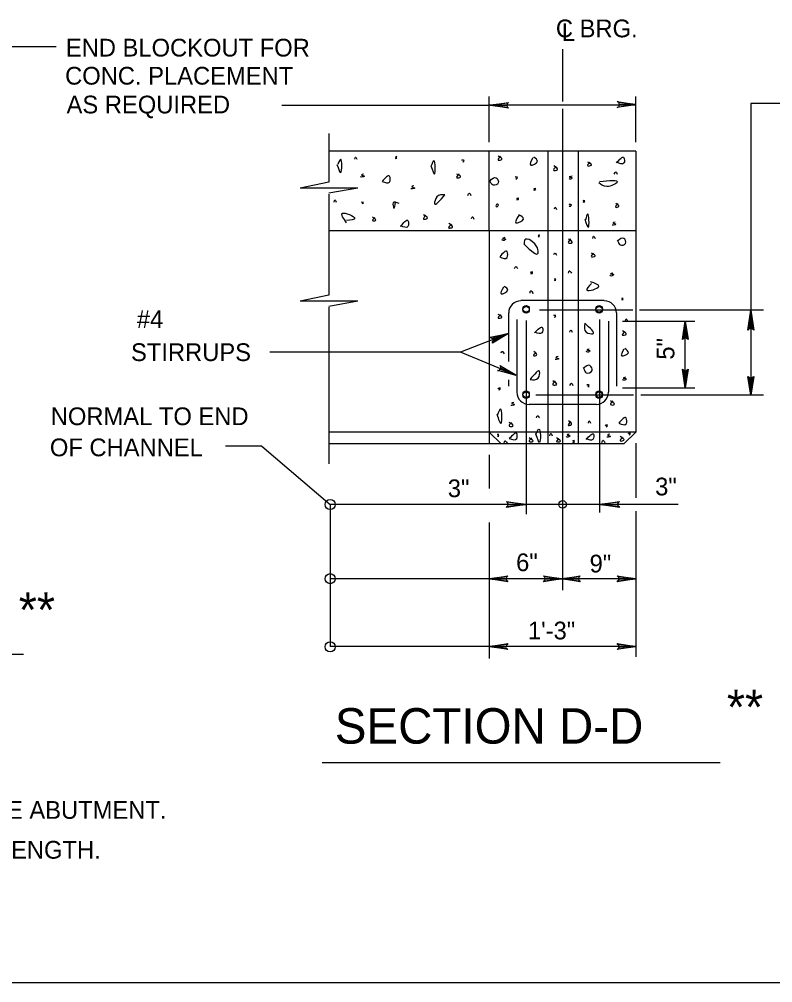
# Model space of a CAD drawing. Extents: x 642009 to 642864, y 298232 to 300014.
# Drawn here: x 642295.7 to 642423.1, y 299434.8 to 299597.7 of the extents above; entities that cross this region are included whole.
import ezdxf

# ---------------------------------------------------------------- set-up
doc = ezdxf.new("R2010")
doc.units = 0
doc.layers.add('1', color=7, linetype='Continuous')
doc.layers.add('2', color=7, linetype='Continuous')

msp = doc.modelspace()

# ---------------------------------------------------------------- linework, layer by layer
at = {"layer": '1'}
msp.add_line((642336.76, 299525.57), (642348.29, 299515.7), dxfattribs=at)
for centre, radius in [((642348.29, 299515.7), 0.854), ((642387.57, 299515.7), 0.648), ((642348.29, 299503.15), 0.854), ((642348.29, 299491.63), 0.854)]:
    msp.add_circle(centre, radius, dxfattribs=at)
at = {"layer": '2'}
for p, q in [((642301.98, 299593.08), (642263.61, 299593.08)), ((642387.57, 299592.7), (642387.57, 299583.83)), ((642375.19, 299576.95), (642375.19, 299584.7)), ((642399.94, 299576.95), (642399.94, 299584.7)), ((642419.39, 299583.49), (642419.39, 299534.2)), ((642426.75, 299583.49), (642419.39, 299583.49)), ((642340.14, 299583.2), (642375.19, 299583.2)), ((642399.94, 299583.2), (642375.19, 299583.2)), ((642387.57, 299582.58), (642387.57, 299501.2)), ((642348.07, 299578.45), (642348.07, 299570.2)), ((642399.94, 299575.45), (642348.07, 299575.45)), ((642375.19, 299561.95), (642375.19, 299575.33)), ((642385.07, 299575.45), (642385.07, 299525.95)), ((642390.19, 299575.45), (642390.19, 299525.95)), ((642399.94, 299575.45), (642399.94, 299527.95)), ((642348.07, 299570.2), (642343.19, 299569.2)), ((642352.94, 299569.2), (642343.19, 299569.2)), ((642352.94, 299569.2), (642348.07, 299568.33)), ((642348.07, 299568.2), (642348.07, 299551.08)), ((642399.94, 299561.95), (642348.07, 299561.95)), ((642375.19, 299561.95), (642375.19, 299527.95)), ((642348.07, 299551.08), (642343.19, 299550.08)), ((642352.94, 299550.08), (642343.19, 299550.08)), ((642352.94, 299550.08), (642348.07, 299549.2)), ((642394.62, 299550.2), (642380.52, 299550.2)), ((642348.07, 299549.08), (642348.07, 299522.58)), ((642378.45, 299548.08), (642378.45, 299539.88)), ((642381.44, 299548.58), (642381.44, 299548.58)), ((642399.44, 299548.58), (642383.69, 299548.58)), ((642393.82, 299548.58), (642393.82, 299548.58)), ((642396.68, 299548.08), (642396.68, 299535.7)), ((642403.69, 299548.58), (642400.57, 299548.58)), ((642417.89, 299548.58), (642403.69, 299548.58)), ((642421.53, 299548.58), (642417.89, 299548.58)), ((642379.82, 299546.95), (642379.82, 299534.7)), ((642381.44, 299546.83), (642381.44, 299514.08)), ((642393.82, 299546.95), (642393.82, 299514.33)), ((642395.32, 299546.7), (642395.32, 299534.7)), ((642397.68, 299546.7), (642402.44, 299546.7)), ((642402.44, 299546.7), (642409.94, 299546.7)), ((642408.32, 299535.45), (642408.32, 299546.7)), ((642378.45, 299544.61), (642370.32, 299541.45)), ((642370.32, 299541.45), (642338.08, 299541.45)), ((642379.69, 299537.58), (642370.32, 299541.45)), ((642378.45, 299536.78), (642378.45, 299535.7)), ((642397.69, 299535.45), (642402.44, 299535.45)), ((642402.44, 299535.45), (642409.94, 299535.45)), ((642381.44, 299534.2), (642381.44, 299534.2)), ((642381.44, 299534.2), (642381.44, 299534.2)), ((642381.44, 299534.2), (642381.44, 299534.2)), ((642399.57, 299534.2), (642383.07, 299534.2)), ((642393.82, 299534.2), (642393.82, 299534.2)), ((642393.82, 299534.2), (642393.82, 299534.2)), ((642403.69, 299534.2), (642400.82, 299534.2)), ((642417.89, 299534.2), (642403.69, 299534.2)), ((642421.53, 299534.2), (642408.07, 299534.2)), ((642393.32, 299532.58), (642381.94, 299532.58)), ((642375.19, 299528.08), (642375.19, 299525.95)), ((642375.19, 299527.95), (642348.07, 299527.95)), ((642375.19, 299527.95), (642377.19, 299525.95)), ((642399.94, 299527.95), (642375.19, 299527.95)), ((642399.94, 299527.95), (642397.94, 299525.95)), ((642336.76, 299525.57), (642330.62, 299525.57)), ((642377.57, 299525.95), (642348.07, 299525.95)), ((642397.94, 299525.95), (642376.57, 299525.95)), ((642399.94, 299526.08), (642399.94, 299516.82)), ((642375.19, 299524.08), (642375.19, 299518.42)), ((642381.44, 299515.7), (642348.29, 299515.7)), ((642348.29, 299515.7), (642348.29, 299491.66)), ((642387.44, 299515.7), (642381.44, 299515.7)), ((642407.13, 299515.7), (642387.69, 299515.7)), ((642399.94, 299514.58), (642399.94, 299489.91)), ((642375.19, 299512.63), (642375.19, 299489.66)), ((642381.44, 299503.14), (642348.29, 299503.14)), ((642399.94, 299503.14), (642375.19, 299503.14)), ((642375.19, 299491.66), (642348.29, 299491.66)), ((642399.94, 299491.66), (642375.19, 299491.66)), ((642208.18, 299490.4), (642296.43, 299490.4)), ((642346.94, 299472.07), (642414.19, 299472.07)), ((642834.66, 299434.82), (642048.66, 299434.82))]:
    msp.add_line(p, q, dxfattribs=at)
for points in [[(642378.32, 299582.83), (642378.19, 299583.08), (642375.32, 299583.2), (642378.32, 299582.83), (642378.44, 299582.7), (642375.32, 299583.2), (642378.19, 299583.33), (642378.32, 299583.58), (642375.32, 299583.2), (642378.44, 299583.7), (642378.32, 299583.58)], [(642397.07, 299583.7), (642397.07, 299583.45), (642399.94, 299583.33), (642397.07, 299583.7), (642396.82, 299583.83), (642399.94, 299583.33), (642397.07, 299583.2), (642397.07, 299582.95), (642399.94, 299583.33), (642396.82, 299582.83), (642397.07, 299582.95)], [(642419.01, 299545.33), (642419.26, 299545.45), (642419.39, 299548.58), (642419.01, 299545.33), (642418.89, 299545.2), (642419.39, 299548.58), (642419.51, 299545.45), (642419.76, 299545.33), (642419.39, 299548.58), (642419.89, 299545.2), (642419.76, 299545.33)], [(642407.94, 299543.7), (642408.19, 299543.83), (642408.32, 299546.7), (642407.94, 299543.7), (642407.82, 299543.58), (642408.32, 299546.7), (642408.44, 299543.83), (642408.69, 299543.7), (642408.32, 299546.7), (642408.82, 299543.58), (642408.69, 299543.7)], [(642375.45, 299543.86), (642375.7, 299543.74), (642378.45, 299544.61), (642375.45, 299543.86), (642375.33, 299543.99), (642378.45, 299544.61), (642375.83, 299543.49), (642375.7, 299543.24), (642378.45, 299544.61), (642375.7, 299542.99), (642375.7, 299543.24)], [(642377.07, 299539.08), (642377.07, 299538.83), (642379.69, 299537.58), (642377.07, 299539.08), (642376.94, 299539.2), (642379.69, 299537.58), (642376.94, 299538.58), (642376.82, 299538.33), (642379.69, 299537.58), (642376.57, 299538.33), (642376.82, 299538.33)], [(642408.69, 299538.45), (642408.44, 299538.33), (642408.32, 299535.45), (642408.69, 299538.45), (642408.82, 299538.58), (642408.32, 299535.45), (642408.19, 299538.33), (642407.94, 299538.45), (642408.32, 299535.45), (642407.82, 299538.58), (642407.94, 299538.45)], [(642419.76, 299537.2), (642419.51, 299537.08), (642419.39, 299534.2), (642419.76, 299537.2), (642419.89, 299537.33), (642419.39, 299534.2), (642419.26, 299537.08), (642419.01, 299537.2), (642419.39, 299534.2), (642418.89, 299537.33), (642419.01, 299537.2)], [(642378.19, 299516.08), (642378.32, 299515.83), (642381.44, 299515.7), (642378.19, 299516.08), (642378.07, 299516.2), (642381.44, 299515.7), (642378.32, 299515.58), (642378.19, 299515.33), (642381.44, 299515.7), (642378.07, 299515.2), (642378.19, 299515.33)], [(642397.07, 299515.33), (642396.94, 299515.58), (642393.82, 299515.7), (642397.07, 299515.33), (642397.19, 299515.2), (642393.82, 299515.7), (642396.94, 299515.83), (642397.07, 299516.08), (642393.82, 299515.7), (642397.19, 299516.2), (642397.07, 299516.08)], [(642378.19, 299502.77), (642378.07, 299503.02), (642375.19, 299503.14), (642378.19, 299502.77), (642378.32, 299502.64), (642375.19, 299503.14), (642378.07, 299503.27), (642378.19, 299503.52), (642375.19, 299503.14), (642378.32, 299503.64), (642378.19, 299503.52)], [(642384.44, 299503.52), (642384.57, 299503.27), (642387.44, 299503.14), (642384.44, 299503.52), (642384.32, 299503.64), (642387.44, 299503.14), (642384.57, 299503.02), (642384.44, 299502.77), (642387.44, 299503.14), (642384.32, 299502.64), (642384.44, 299502.77)], [(642390.44, 299502.77), (642390.32, 299503.02), (642387.44, 299503.14), (642390.44, 299502.77), (642390.57, 299502.64), (642387.44, 299503.14), (642390.32, 299503.27), (642390.44, 299503.52), (642387.44, 299503.14), (642390.57, 299503.64), (642390.44, 299503.52)], [(642396.94, 299503.52), (642397.07, 299503.27), (642399.94, 299503.14), (642396.94, 299503.52), (642396.82, 299503.64), (642399.94, 299503.14), (642397.07, 299503.02), (642396.94, 299502.77), (642399.94, 299503.14), (642396.82, 299502.64), (642396.94, 299502.77)], [(642378.19, 299491.28), (642378.07, 299491.41), (642375.19, 299491.66), (642378.19, 299491.28), (642378.32, 299491.16), (642375.19, 299491.66), (642378.07, 299491.78), (642378.19, 299492.03), (642375.19, 299491.66), (642378.32, 299492.16), (642378.19, 299492.03)], [(642396.94, 299492.03), (642397.07, 299491.78), (642399.94, 299491.66), (642396.94, 299492.03), (642396.82, 299492.16), (642399.94, 299491.66), (642397.07, 299491.53), (642396.94, 299491.28), (642399.94, 299491.66), (642396.82, 299491.16), (642396.94, 299491.28)]]:
    msp.add_lwpolyline(points, dxfattribs=at)
for centre in [(642381.4, 299548.78), (642393.77, 299548.78), (642381.4, 299548.61), (642393.77, 299548.61), (642381.4, 299534.34), (642381.4, 299534.17), (642393.77, 299534.34), (642393.77, 299534.17)]:
    msp.add_circle(centre, 0.549, dxfattribs=at)
for centre, start, end in [((642380.52, 299548.08), 90, 180), ((642394.62, 299548.08), 0, 90), ((642381.91, 299534.68), 180, 270), ((642393.26, 299534.68), 270, 0)]:
    msp.add_arc(centre, 2.06, start, end, dxfattribs=at)
for points in [[(642349.44, 299573.2), (642350.07, 299571.83), (642350.07, 299574.08), (642349.57, 299573.2)], [(642352.44, 299574.08), (642352.57, 299574.45), (642352.82, 299574.08)], [(642359.57, 299574.2), (642359.32, 299574.2), (642359.57, 299574.33), (642359.32, 299574.45), (642359.57, 299574.58)], [(642365.32, 299572.95), (642365.94, 299571.58), (642365.82, 299573.83), (642365.32, 299572.83)], [(642370.82, 299573.58), (642370.69, 299573.58), (642370.94, 299573.83), (642370.57, 299573.95), (642370.94, 299573.95)], [(642377.07, 299574.58), (642376.69, 299573.95), (642377.32, 299574.08), (642376.69, 299574.58)], [(642382.57, 299574.33), (642382.19, 299573.08), (642383.32, 299573.7), (642382.69, 299574.45)], [(642396.69, 299573.45), (642397.94, 299574.33), (642397.94, 299573.45), (642396.69, 299573.58)], [(642386.44, 299572.83), (642386.07, 299572.2), (642386.69, 299572.33), (642386.07, 299572.95)], [(642392.19, 299573.58), (642391.82, 299572.95), (642392.44, 299573.08), (642391.82, 299573.58)], [(642353.94, 299571.58), (642353.57, 299571.45), (642354.07, 299571.2), (642353.69, 299571.08), (642353.44, 299571.08)], [(642357.07, 299570.33), (642358.32, 299571.2), (642358.32, 299570.2), (642357.07, 299570.33)], [(642370.07, 299571.58), (642369.69, 299570.95), (642370.32, 299571.08), (642369.69, 299571.58)], [(642375.32, 299570.45), (642375.82, 299569.7), (642376.69, 299570.08), (642376.32, 299570.95), (642375.32, 299570.45)], [(642379.82, 299570.7), (642379.69, 299570.7), (642379.94, 299570.95), (642379.57, 299571.08), (642379.94, 299571.08)], [(642389.19, 299571.2), (642388.69, 299571.08), (642389.19, 299570.95), (642388.82, 299570.7), (642388.69, 299570.83)], [(642393.82, 299570.33), (642396.82, 299570.2), (642395.07, 299569.45), (642393.69, 299570.08)], [(642396.32, 299571.58), (642396.57, 299571.95), (642396.82, 299571.58)], [(642362.44, 299569.58), (642362.07, 299569.45), (642362.57, 299569.2), (642362.19, 299569.08), (642361.94, 299569.08)], [(642382.94, 299568.83), (642382.69, 299568.83), (642383.07, 299569.08), (642382.69, 299569.08), (642383.07, 299569.2)], [(642348.94, 299566.83), (642349.07, 299567.2), (642349.32, 299566.83)], [(642367.69, 299568.08), (642365.94, 299566.58), (642366.32, 299567.7), (642367.69, 299568.08)], [(642371.57, 299567.95), (642371.82, 299568.33), (642372.07, 299567.95)], [(642380.07, 299567.2), (642379.82, 299567.2), (642380.19, 299567.33), (642379.82, 299567.45), (642380.19, 299567.58)], [(642353.94, 299566.58), (642353.69, 299566.58), (642353.94, 299566.7), (642353.57, 299566.83), (642353.94, 299566.83)], [(642359.94, 299566.58), (642358.94, 299566.7), (642359.07, 299565.83), (642359.32, 299566.83)], [(642376.32, 299566.08), (642376.32, 299566.33), (642376.69, 299566.45), (642376.57, 299566.08), (642376.32, 299566.08)], [(642386.19, 299565.7), (642386.32, 299565.95), (642386.57, 299565.58)], [(642388.94, 299566.08), (642388.69, 299566.08), (642389.07, 299566.33), (642388.69, 299566.45), (642389.07, 299566.45)], [(642391.32, 299566.83), (642391.07, 299566.83), (642391.32, 299566.95), (642391.07, 299567.08), (642391.32, 299567.08)], [(642396.94, 299566.58), (642396.57, 299565.95), (642397.07, 299566.08), (642396.57, 299566.58)], [(642351.07, 299563.33), (642350.32, 299564.95), (642352.44, 299564.08), (642351.07, 299563.7)], [(642355.82, 299564.2), (642355.44, 299563.7), (642355.94, 299563.7), (642355.44, 299564.33)], [(642360.19, 299562.7), (642361.44, 299563.7), (642361.44, 299562.7), (642360.19, 299562.83)], [(642364.44, 299564.58), (642364.07, 299563.95), (642364.69, 299564.08), (642364.07, 299564.7)], [(642372.19, 299564.08), (642372.32, 299564.33), (642372.57, 299563.95)], [(642380.19, 299564.58), (642379.69, 299563.33), (642380.94, 299563.95), (642380.19, 299564.7)], [(642391.32, 299563.95), (642391.94, 299562.58), (642391.82, 299564.83), (642391.44, 299563.83)], [(642368.82, 299563.08), (642368.32, 299562.45), (642368.94, 299562.58), (642368.32, 299563.2)], [(642396.44, 299563.45), (642396.07, 299563.33), (642396.57, 299563.08), (642396.19, 299562.95), (642395.94, 299562.95)], [(642377.82, 299560.83), (642377.44, 299560.7), (642377.94, 299560.58), (642377.57, 299560.33), (642377.32, 299560.45)], [(642381.19, 299559.58), (642383.44, 299558.2), (642383.32, 299559.08), (642381.19, 299560.45), (642381.07, 299559.58)], [(642383.69, 299560.95), (642383.44, 299560.95), (642383.69, 299561.2), (642383.44, 299561.2), (642383.69, 299561.33)], [(642392.69, 299560.7), (642392.82, 299561.08), (642393.07, 299560.7)], [(642396.94, 299560.2), (642397.32, 299559.58), (642398.19, 299559.83), (642397.94, 299560.7), (642396.82, 299560.2)], [(642388.94, 299560.58), (642388.57, 299559.95), (642389.19, 299559.95), (642388.57, 299560.58)], [(642376.94, 299557.58), (642378.19, 299558.45), (642378.19, 299557.45), (642376.94, 299557.58)], [(642386.07, 299557.95), (642386.19, 299558.2), (642386.57, 299557.83)], [(642392.82, 299558.2), (642392.44, 299557.58), (642393.07, 299557.7), (642392.44, 299558.2)], [(642379.44, 299555.58), (642379.69, 299555.95), (642379.94, 299555.58)], [(642382.44, 299554.7), (642382.19, 299554.7), (642382.57, 299554.83), (642382.19, 299554.95), (642382.57, 299555.08)], [(642388.57, 299554.83), (642388.69, 299555.2), (642389.07, 299554.83)], [(642396.07, 299554.83), (642395.69, 299554.7), (642396.19, 299554.58), (642395.82, 299554.33), (642395.57, 299554.45)], [(642377.57, 299552.45), (642377.19, 299551.33), (642378.32, 299551.95), (642377.69, 299552.58)], [(642386.44, 299553.58), (642386.19, 299553.58), (642386.44, 299553.7), (642386.19, 299553.83), (642386.44, 299553.83)], [(642392.44, 299553.08), (642391.69, 299551.95), (642393.69, 299552.58), (642392.32, 299553.33)], [(642382.07, 299551.45), (642382.19, 299551.83), (642382.57, 299551.33)], [(642397.82, 299550.33), (642397.57, 299550.33), (642397.82, 299550.45), (642397.57, 299550.58), (642397.82, 299550.58)], [(642377.07, 299547.83), (642376.69, 299547.2), (642377.32, 299547.33), (642376.69, 299547.83)], [(642386.32, 299547.33), (642386.19, 299547.33), (642386.44, 299547.58), (642386.07, 299547.7), (642386.44, 299547.7)], [(642391.32, 299546.33), (642392.69, 299544.58), (642391.57, 299544.83), (642391.32, 299546.33)], [(642398.19, 299546.7), (642398.32, 299547.08), (642398.57, 299546.7)], [(642382.82, 299544.7), (642384.19, 299545.58), (642384.07, 299544.7), (642382.94, 299544.83)], [(642388.82, 299544.83), (642388.94, 299545.2), (642389.19, 299544.83)], [(642398.07, 299544.95), (642397.69, 299544.33), (642398.32, 299544.45), (642397.69, 299545.08)], [(642377.19, 299541.33), (642377.32, 299541.58), (642377.69, 299541.2)], [(642383.07, 299541.45), (642382.69, 299540.83), (642383.19, 299540.95), (642382.69, 299541.58)], [(642392.07, 299541.95), (642391.69, 299541.83), (642392.19, 299541.7), (642391.82, 299541.45), (642391.57, 299541.58)], [(642397.94, 299541.95), (642397.57, 299540.83), (642398.69, 299541.33), (642398.07, 299542.08)], [(642386.82, 299540.7), (642386.44, 299540.58), (642386.94, 299540.33), (642386.57, 299540.2), (642386.32, 299540.2)], [(642382.07, 299536.83), (642383.69, 299538.2), (642383.44, 299537.08), (642382.07, 299536.83)], [(642391.19, 299538.7), (642391.57, 299537.95), (642392.57, 299538.33), (642392.19, 299539.2), (642391.07, 299538.7)], [(642386.32, 299536.58), (642385.94, 299535.95), (642386.57, 299535.95), (642385.94, 299536.58)], [(642388.82, 299535.83), (642389.07, 299536.2), (642389.32, 299535.83)], [(642398.19, 299537.2), (642397.82, 299537.08), (642398.32, 299536.95), (642397.94, 299536.7), (642397.69, 299536.83)], [(642376.94, 299535.08), (642376.82, 299535.08), (642377.07, 299535.2), (642376.69, 299535.33), (642377.07, 299535.45)], [(642392.07, 299535.58), (642391.82, 299535.58), (642392.07, 299535.83), (642391.69, 299535.95), (642392.07, 299535.95)], [(642379.32, 299532.95), (642378.94, 299532.83), (642379.44, 299532.58), (642379.07, 299532.45), (642378.82, 299532.45)], [(642396.07, 299533.2), (642395.69, 299532.58), (642396.32, 299532.58), (642395.69, 299533.2)], [(642376.44, 299530.95), (642377.19, 299529.45), (642377.07, 299531.83), (642376.57, 299530.83)], [(642383.19, 299530.33), (642383.32, 299530.7), (642383.69, 299530.33)], [(642388.94, 299529.7), (642388.57, 299529.08), (642389.07, 299529.2), (642388.57, 299529.83)], [(642391.94, 299529.45), (642392.07, 299529.83), (642392.32, 299529.45)], [(642397.07, 299529.45), (642398.32, 299530.33), (642398.32, 299529.33), (642397.07, 299529.45)], [(642378.94, 299529.58), (642378.57, 299528.95), (642379.19, 299528.95), (642378.57, 299529.58)], [(642383.07, 299527.58), (642383.69, 299526.2), (642383.57, 299528.45), (642383.07, 299527.58)], [(642395.07, 299528.83), (642394.94, 299528.83), (642395.19, 299528.95), (642394.82, 299529.08), (642395.19, 299529.2)], [(642376.82, 299527.2), (642376.57, 299527.2), (642376.82, 299527.45), (642376.57, 299527.58), (642376.82, 299527.58)], [(642377.69, 299526.08), (642377.82, 299526.45), (642378.19, 299526.08)], [(642378.57, 299526.83), (642379.82, 299527.7), (642379.82, 299526.83), (642378.57, 299526.83)], [(642382.32, 299526.95), (642381.94, 299526.33), (642382.57, 299526.33), (642381.94, 299526.95)], [(642385.44, 299527.33), (642385.57, 299527.7), (642385.82, 299527.33)], [(642386.94, 299526.83), (642386.57, 299526.33), (642387.19, 299526.33), (642386.57, 299526.95)], [(642388.69, 299527.58), (642388.32, 299527.45), (642388.82, 299527.33), (642388.32, 299527.08), (642388.19, 299527.2)], [(642389.57, 299526.2), (642389.32, 299526.2), (642389.57, 299526.33), (642389.32, 299526.45), (642389.57, 299526.58)], [(642391.57, 299526.7), (642392.82, 299527.58), (642392.69, 299526.7), (642391.57, 299526.83)], [(642394.19, 299526.2), (642394.44, 299526.58), (642394.69, 299526.08)], [(642395.57, 299527.58), (642395.19, 299527.45), (642395.69, 299527.2), (642395.32, 299527.08), (642395.07, 299527.08)], [(642397.69, 299527.08), (642397.32, 299526.45), (642397.94, 299526.58), (642397.32, 299527.2)], [(642398.94, 299527.45), (642398.82, 299527.45), (642399.07, 299527.58), (642398.69, 299527.7), (642399.07, 299527.83)]]:
    msp.add_spline(points, degree=3, dxfattribs=at)

# ---------------------------------------------------------------- texts
for s, height, p in [('C BRG.', 3, (642386.44, 299594.7)), ('L', 3, (642387.44, 299594.08)), ('END BLOCKOUT FOR', 3, (642303.61, 299591.45)), ('CONC. PLACEMENT', 3, (642303.48, 299586.7)), ('AS REQUIRED', 3, (642303.73, 299581.83)), ('#4', 3, (642315.61, 299545.54)), ('STIRRUPS', 3, (642314.62, 299539.95)), ('NORMAL TO END', 3, (642301.06, 299529.11)), ('OF CHANNEL', 3, (642300.91, 299523.85)), ('3"', 3, (642368.17, 299516.93)), ('3"', 3, (642403.22, 299517.23)), ('6"', 3, (642379.72, 299504.42)), ('9"', 3, (642392.14, 299504.2)), ('**', 5.88, (642295.65, 299494.94)), ('1\'-3"', 3, (642381.72, 299492.88)), ('**', 5.88, (642415.35, 299478.5)), ('SECTION D-D', 6, (642349.07, 299475.25)), ('POUR DIAPHRAGM CONCRETE BEFORE SETTING THE BEAM ON THE ABUTMENT.', 3, (642161.7, 299462.54)), ('PLACE BEAM WHEN DIAPH. HAS ATTAINED 80% OF ITS DESIGN STRENGTH.', 3, (642161.71, 299455.8))]:
    msp.add_text(s, height=height, dxfattribs=at).set_placement(p)
msp.add_text('5"', height=3, rotation=90, dxfattribs=at).set_placement((642406.47, 299540.19))

doc.saveas('drawing.dxf')
